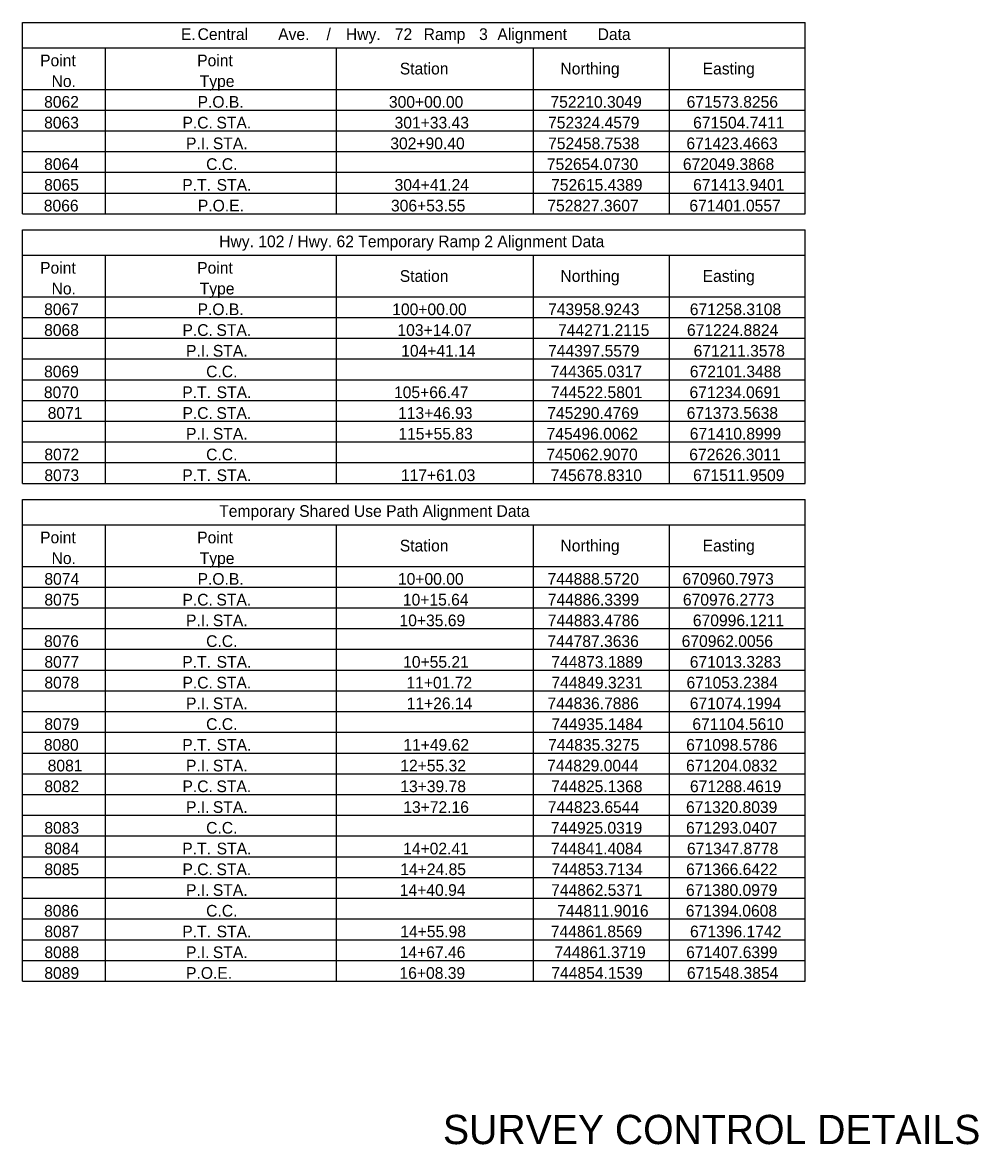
# Model space of a CAD drawing. Extents: x 672566 to 676329, y 739687 to 740710.
# Drawn here: x 674192.9 to 674601.1, y 739689.4 to 740168.4 of the extents above; entities that cross this region are included whole.
import ezdxf

# ---------------------------------------------------------------- set-up
doc = ezdxf.new("R2010")
doc.units = 0
doc.layers.add('R_Border Notes', color=7, linetype='Continuous')
doc.layers.add('S_BASELINE', color=7, linetype='Continuous')

msp = doc.modelspace()

# ---------------------------------------------------------------- linework, layer by layer
at = {"layer": 'S_BASELINE'}
for p, q in [((674192.88, 740168.42), (674527.08, 740168.42)), ((674192.88, 740086.74), (674192.88, 740168.42)), ((674527.08, 740086.74), (674527.08, 740168.42)), ((674192.88, 740157.57), (674527.08, 740157.57)), ((674228.29, 740086.74), (674228.29, 740157.57)), ((674327, 740086.74), (674327, 740157.57)), ((674411.1, 740086.74), (674411.1, 740157.57)), ((674469.09, 740086.74), (674469.09, 740157.57)), ((674192.88, 740139.86), (674527.08, 740139.86)), ((674192.88, 740139.86), (674228.29, 740139.86)), ((674192.88, 740131.01), (674527.08, 740131.01)), ((674192.88, 740122.15), (674527.08, 740122.15)), ((674192.88, 740113.3), (674527.08, 740113.3)), ((674192.88, 740104.45), (674527.08, 740104.45)), ((674192.88, 740095.6), (674527.08, 740095.6)), ((674192.88, 740086.74), (674527.08, 740086.74)), ((674192.88, 740079.89), (674527.08, 740079.89)), ((674192.88, 739971.65), (674192.88, 740079.89)), ((674527.08, 739971.65), (674527.08, 740079.89)), ((674192.88, 740069.04), (674527.08, 740069.04)), ((674228.29, 739971.65), (674228.29, 740069.04)), ((674327, 739971.65), (674327, 740069.04)), ((674411.1, 739971.65), (674411.1, 740069.04)), ((674469.09, 739971.65), (674469.09, 740069.04)), ((674192.88, 740051.33), (674527.08, 740051.33)), ((674192.88, 740051.33), (674228.29, 740051.33)), ((674192.88, 740042.48), (674527.08, 740042.48)), ((674192.88, 740033.62), (674527.08, 740033.62)), ((674192.88, 740024.77), (674527.08, 740024.77)), ((674192.88, 740015.92), (674527.08, 740015.92)), ((674192.88, 740007.07), (674527.08, 740007.07)), ((674192.88, 739998.21), (674527.08, 739998.21)), ((674192.88, 739989.36), (674527.08, 739989.36)), ((674192.88, 739980.51), (674527.08, 739980.51)), ((674192.88, 739971.65), (674527.08, 739971.65)), ((674192.88, 739964.8), (674527.08, 739964.8)), ((674192.88, 739759.18), (674192.88, 739964.8)), ((674527.08, 739759.18), (674527.08, 739964.8)), ((674192.88, 739953.95), (674527.08, 739953.95)), ((674228.29, 739759.18), (674228.29, 739953.95)), ((674327, 739759.18), (674327, 739953.95)), ((674411.1, 739759.18), (674411.1, 739953.95)), ((674469.09, 739759.18), (674469.09, 739953.95)), ((674192.88, 739936.24), (674527.08, 739936.24)), ((674192.88, 739936.24), (674228.29, 739936.24)), ((674192.88, 739927.39), (674527.08, 739927.39)), ((674192.88, 739918.54), (674527.08, 739918.54)), ((674192.88, 739909.68), (674527.08, 739909.68)), ((674192.88, 739900.83), (674527.08, 739900.83)), ((674192.88, 739891.98), (674527.08, 739891.98)), ((674192.88, 739883.12), (674527.08, 739883.12)), ((674192.88, 739874.27), (674527.08, 739874.27)), ((674192.88, 739865.42), (674527.08, 739865.42)), ((674192.88, 739856.56), (674527.08, 739856.56)), ((674192.88, 739847.71), (674527.08, 739847.71)), ((674192.88, 739838.86), (674527.08, 739838.86)), ((674192.88, 739830.01), (674527.08, 739830.01)), ((674192.88, 739821.15), (674527.08, 739821.15)), ((674192.88, 739812.3), (674527.08, 739812.3)), ((674192.88, 739803.45), (674527.08, 739803.45)), ((674192.88, 739794.59), (674527.08, 739794.59)), ((674192.88, 739785.74), (674527.08, 739785.74)), ((674192.88, 739776.89), (674527.08, 739776.89)), ((674192.88, 739768.03), (674527.08, 739768.03)), ((674192.88, 739759.18), (674527.08, 739759.18))]:
    msp.add_line(p, q, dxfattribs=at)

# ---------------------------------------------------------------- texts
at = {"layer": 'R_Border Notes'}
msp.add_text('SURVEY CONTROL DETAILS', height=12.5, rotation=360, dxfattribs=at).set_placement((674372.41, 739689.62))
at = {"layer": 'S_BASELINE'}
for s, p in [('E.', (674260.53, 740160.92)), (' Central', (674265.8, 740160.92)), (' Ave.', (674300.2, 740160.92)), (' /', (674320.85, 740160.92)), (' Hwy.', (674329.11, 740160.92)), (' 72', (674349.99, 740160.92)), (' Ramp', (674362.3, 740160.92)), (' 3', (674385.97, 740160.92)), (' Alignment', (674393.79, 740160.92)), (' Data', (674436.58, 740160.92)), ('Point', (674200.42, 740149.71)), ('Point', (674267.48, 740149.71)), ('Station', (674353.97, 740146.22)), ('Northing', (674422.56, 740146.22)), ('Easting', (674483.26, 740146.22)), ('No.', (674205.31, 740140.86)), ('Type', (674268.56, 740140.86)), ('8062', (674202.13, 740132.01)), ('P.O.B.', (674267.65, 740132.01)), ('300+00.00', (674349.33, 740132.01)), ('752210.3049', (674418.29, 740132.01)), ('671573.8256', (674476.44, 740132.01)), ('8063', (674202.13, 740123.15)), ('P.C.', (674261.19, 740123.15)), (' STA.', (674273.85, 740123.15)), ('301+33.43', (674351.75, 740123.15)), ('752324.4579', (674417.27, 740123.15)), ('671504.7411', (674479.21, 740123.15)), ('P.I.', (674262.72, 740114.3)), (' STA.', (674272.31, 740114.3)), ('302+90.40', (674349.92, 740114.3)), ('752458.7538', (674417.29, 740114.3)), ('671423.4663', (674476.34, 740114.3)), ('8064', (674202.13, 740105.45)), ('C.C.', (674271.31, 740105.45)), ('752654.0730', (674416.76, 740105.45)), ('672049.3868', (674474.84, 740105.45)), ('8065', (674202.13, 740096.59)), ('P.T.', (674261.11, 740096.59)), (' STA.', (674273.93, 740096.59)), ('304+41.24', (674351.75, 740096.59)), ('752615.4389', (674418.57, 740096.59)), ('671413.9401', (674479.21, 740096.59)), ('8066', (674201.99, 740087.74)), ('P.O.E.', (674267.77, 740087.74)), ('306+53.55', (674350.21, 740087.74)), ('752827.3607', (674416.97, 740087.74)), ('671401.0557', (674477.6, 740087.74)), ('Hwy. 102 / Hwy. 62 Temporary Ramp 2 Alignment Data', (674276.87, 740072.46)), ('Point', (674200.42, 740061.18)), ('Point', (674267.48, 740061.18)), ('Station', (674353.97, 740057.69)), ('Northing', (674422.56, 740057.69)), ('Easting', (674483.26, 740057.69)), ('No.', (674205.31, 740052.33)), ('Type', (674268.56, 740052.33)), ('8067', (674202.13, 740043.48)), ('P.O.B.', (674267.65, 740043.48)), ('100+00.00', (674350.74, 740043.48)), ('743958.9243', (674417.29, 740043.48)), ('671258.3108', (674477.79, 740043.48)), ('8068', (674202.13, 740034.62)), ('P.C.', (674261.19, 740034.62)), (' STA.', (674273.85, 740034.62)), ('103+14.07', (674352.97, 740034.62)), ('744271.2115', (674421.53, 740034.62)), ('671224.8824', (674476.57, 740034.62)), ('P.I.', (674262.72, 740025.77)), (' STA.', (674272.31, 740025.77)), ('104+41.14', (674354.58, 740025.77)), ('744397.5579', (674417.27, 740025.77)), ('671211.3578', (674479.4, 740025.77)), ('8069', (674202.11, 740016.92)), ('C.C.', (674271.31, 740016.92)), ('744365.0317', (674418.39, 740016.92)), ('672101.3488', (674477.79, 740016.92)), ('8070', (674202.03, 740008.06)), ('P.T.', (674261.11, 740008.06)), (' STA.', (674273.93, 740008.06)), ('105+66.47', (674351.51, 740008.06)), ('744522.5801', (674418.51, 740008.06)), ('671234.0691', (674477.67, 740008.06)), ('8071', (674203.66, 739999.21)), ('P.C.', (674261.19, 739999.21)), (' STA.', (674273.85, 739999.21)), ('113+46.93', (674353.24, 739999.21)), ('745290.4769', (674416.95, 739999.21)), ('671373.5638', (674476.45, 739999.21)), ('P.I.', (674262.72, 739990.36)), (' STA.', (674272.31, 739990.36)), ('115+55.83', (674353.36, 739990.36)), ('745496.0062', (674416.66, 739990.36)), ('671410.8999', (674477.77, 739990.36)), ('8072', (674202.24, 739981.5)), ('C.C.', (674271.31, 739981.5)), ('745062.9070', (674416.56, 739981.5)), ('672626.3011', (674477.56, 739981.5)), ('8073', (674202.24, 739972.65)), ('P.T.', (674261.11, 739972.65)), (' STA.', (674273.93, 739972.65)), ('117+61.03', (674354.46, 739972.65)), ('745678.8310', (674418.37, 739972.65)), ('671511.9509', (674479.19, 739972.65)), ('Temporary Shared Use Path Alignment Data', (674276.87, 739957.37)), ('Point', (674200.42, 739946.09)), ('Point', (674267.48, 739946.09)), ('Station', (674353.97, 739942.6)), ('Northing', (674422.56, 739942.6)), ('Easting', (674483.26, 739942.6)), ('No.', (674205.31, 739937.24)), ('Type', (674268.56, 739937.24)), ('8074', (674202.24, 739928.39)), ('P.O.B.', (674267.65, 739928.39)), ('10+00.00', (674353.18, 739928.39)), ('744888.5720', (674417.07, 739928.39)), ('670960.7973', (674474.65, 739928.39)), ('8075', (674202.24, 739919.53)), ('P.C.', (674261.19, 739919.53)), (' STA.', (674273.85, 739919.53)), ('10+15.64', (674355.29, 739919.53)), ('744886.3399', (674417.15, 739919.53)), ('670976.2773', (674474.84, 739919.53)), (' STA.', (674272.31, 739910.68)), ('10+35.69', (674353.85, 739910.68)), ('744883.4786', (674417.15, 739910.68)), ('670996.1211', (674479.09, 739910.68)), ('P.I.', (674262.72, 739910.68)), ('8076', (674202.11, 739901.83)), ('C.C.', (674271.31, 739901.83)), ('744787.3636', (674417.03, 739901.83)), ('670962.0056', (674474.31, 739901.83)), ('8077', (674202.24, 739892.97)), ('P.T.', (674261.11, 739892.97)), (' STA.', (674273.93, 739892.97)), ('10+55.21', (674355.4, 739892.97)), ('744873.1889', (674418.68, 739892.97)), ('671013.3283', (674477.79, 739892.97)), ('8078', (674202.24, 739884.12)), ('P.C.', (674261.19, 739884.12)), (' STA.', (674273.85, 739884.12)), ('11+01.72', (674356.82, 739884.12)), ('744849.3231', (674418.7, 739884.12)), ('671053.2384', (674476.38, 739884.12)), ('P.I.', (674262.72, 739875.27)), (' STA.', (674272.31, 739875.27)), ('11+26.14', (674356.9, 739875.27)), ('744836.7886', (674417.03, 739875.27)), ('671074.1994', (674477.79, 739875.27)), ('8079', (674202.22, 739866.42)), ('C.C.', (674271.31, 739866.42)), ('744935.1484', (674418.7, 739866.42)), ('671104.5610', (674478.87, 739866.42)), ('8080', (674202.03, 739857.56)), ('P.T.', (674261.11, 739857.56)), (' STA.', (674273.93, 739857.56)), ('11+49.62', (674355.48, 739857.56)), ('744835.3275', (674417.29, 739857.56)), ('671098.5786', (674476.24, 739857.56)), ('8081', (674203.66, 739848.71)), ('P.I.', (674262.72, 739848.71)), (' STA.', (674272.31, 739848.71)), ('12+55.32', (674354.19, 739848.71)), ('744829.0044', (674416.89, 739848.71)), ('671204.0832', (674476.18, 739848.71)), ('8082', (674202.24, 739839.86)), ('P.C.', (674261.19, 739839.86)), (' STA.', (674273.85, 739839.86)), ('13+39.78', (674354.19, 739839.86)), ('744825.1368', (674418.59, 739839.86)), ('671288.4619', (674477.85, 739839.86)), ('P.I.', (674262.72, 739831)), (' STA.', (674272.31, 739831)), ('13+72.16', (674355.46, 739831)), ('744823.6544', (674417.17, 739831)), ('671320.8039', (674476.16, 739831)), ('8083', (674202.24, 739822.15)), ('C.C.', (674271.31, 739822.15)), ('744925.0319', (674418.49, 739822.15)), ('671293.0407', (674476.18, 739822.15)), ('8084', (674202.24, 739813.3)), ('P.T.', (674261.11, 739813.3)), (' STA.', (674273.93, 739813.3)), ('14+02.41', (674355.4, 739813.3)), ('744841.4084', (674418.51, 739813.3)), ('671347.8778', (674476.57, 739813.3)), ('8085', (674202.24, 739804.44)), ('P.C.', (674261.19, 739804.44)), (' STA.', (674273.85, 739804.44)), ('14+24.85', (674354.19, 739804.44)), ('744853.7134', (674418.7, 739804.44)), ('671366.6422', (674476.22, 739804.44)), ('P.I.', (674262.72, 739795.59)), (' STA.', (674272.31, 739795.59)), ('14+40.94', (674353.99, 739795.59)), ('744862.5371', (674418.59, 739795.59)), ('671380.0979', (674476.16, 739795.59)), ('8086', (674202.11, 739786.74)), ('C.C.', (674271.31, 739786.74)), ('744811.9016', (674421.2, 739786.74)), ('671394.0608', (674476.06, 739786.74)), ('8087', (674202.24, 739777.89)), ('P.T.', (674261.11, 739777.89)), (' STA.', (674273.93, 739777.89)), ('14+55.98', (674354.19, 739777.89)), ('744861.8569', (674418.45, 739777.89)), ('671396.1742', (674477.87, 739777.89)), ('8088', (674202.24, 739769.03)), ('P.I.', (674262.72, 739769.03)), (' STA.', (674272.31, 739769.03)), ('14+67.46', (674353.93, 739769.03)), ('744861.3719', (674419.98, 739769.03)), ('671407.6399', (674476.24, 739769.03)), ('8089', (674202.22, 739760.18)), ('P.O.E.', (674262.72, 739760.18)), ('16+08.39', (674353.85, 739760.18)), ('744854.1539', (674418.68, 739760.18)), ('671548.3854', (674476.57, 739760.18))]:
    msp.add_text(s, height=4.994, dxfattribs=at).set_placement(p)

doc.saveas('drawing.dxf')
